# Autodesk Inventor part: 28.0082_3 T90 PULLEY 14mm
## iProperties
Created: 2006-12
Document SubType Name: Modeling
Designer: Andy Moles
Part Number: 28.0082_3 T90 PULLEY 14mm
Material: Aluminum-6061
Density: 2.71 g/cm^3
Author: Andy Moles
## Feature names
1. Extrusion1
2. Extrusion3
3. Extrusion4
4. Extrusion6
5. Mirror1
6. Extrusion7
7. Chamfer1
8. Chamfer2
